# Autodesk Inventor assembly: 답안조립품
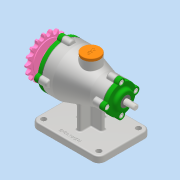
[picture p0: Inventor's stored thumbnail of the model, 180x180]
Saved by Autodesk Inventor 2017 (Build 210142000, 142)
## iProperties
Part Number: 답안조립품
Material: 일반
Document SubType Name: Assembly
Designer: 222
Author: 222
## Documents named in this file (15)
- C:\Users\222\Desktop\701206V1014\답안조립품.iam
- C:\Users\222\Desktop\701206V1014\01본체.ipt
- C:\Users\222\Desktop\701206V1014\개스킷 A.ipt
- C:\Users\222\Desktop\701206V1014\개스킷 B.ipt
- C:\Users\222\Desktop\701206V1014\뒤커버.ipt
- C:\Users\222\Desktop\701206V1014\마개.ipt
- C:\Users\222\Desktop\701206V1014\베어링 6200.ipt
- C:\Users\222\Desktop\701206V1014\베어링 6203.ipt
- C:\Users\222\Desktop\701206V1014\볼트 M5.ipt
- C:\Users\222\Desktop\701206V1014\스프로킷.ipt
- C:\Users\222\Desktop\701206V1014\앞커버.ipt
- C:\Users\222\Desktop\701206V1014\오일 실 10 20 7.ipt
- C:\Users\222\Desktop\701206V1014\오일 실 17 30 8.ipt
- C:\Users\222\Desktop\701206V1014\축.ipt
- C:\Users\222\Desktop\701206V1014\키 4x4x14.ipt
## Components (3 placed, 3 different names)
1. 01본체:1 — 각도:1, 각도:2
2. 개스킷 A:1
3. 개스킷 B:1
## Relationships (2: Angle 2)
- 각도:1 [Angle]: 01본체:1
- 각도:2 [Angle]: 01본체:1
